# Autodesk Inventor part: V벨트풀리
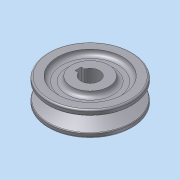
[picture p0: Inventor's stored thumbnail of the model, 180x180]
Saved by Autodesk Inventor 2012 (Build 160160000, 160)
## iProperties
Created: 2015-03
Part Number: V벨트풀리
Material: 강
Document SubType Name: Modeling
Designer: KYOUNG IL JANG
Density: 1 g/cm^3
CustomPartVersion: 1
Author: KYOUNG IL JANG
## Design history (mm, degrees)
sketch "주 스케치"
  geometry: L1 (0, 16)-(27, 16); L2 (27, 16)-(27, 12.861); L3 (27, 12.861)-(16, 9.498); L4 (16, 9.498)-(16, 6.502); L5 (16, 6.502)-(27, 3.139); L6 (27, 3.139)-(27, 0); L7 (27, 0)-(0, 0); L8 (25, 12.25)-(25, 3.75); L9 (16, 8)-(25, 8); L10 (27, 12.861)-(27, 3.139); L11 (0, -3)-(0, 18) reference; L12 (0, 0)-(0, 16)
  constraints: 22 end point, 5 perpendicular, 2 collinear, 2 midpoint, 2 point on line, 1 parallel
  dimensions: "d0" = 8.5 distance of L8.start L8.end (= da_Bw); "d1" = 34 deg angle of L3 L5 (= da_Alfa); "d2" = 2 distance between parallel lines of L2 L8 (= da_c); "d6" = 16 distance between parallel lines of L7 L1 (computed from d5, da_ng, da_Sg); "d21" = 50 diameter of L8 L11 (= da_Dw); "d25" = 11 distance between parallel lines of L4 L10 (= da_Hd); "d27" = 8 distance between parallel lines of L7 L9 (= da_Se)
node "벨트 평면"
revolve "본체" stored, may be unused: angle "d7" = 90 deg
revolve "그루브" stored, may be unused: angle "d15" = 90 deg
feature "허브 키홈"
fillet "모깎기3" dims "d28" = 0.5, "d29" = 1, "d30" = 1
sketch "스케치2"
  geometry: C1 r 12 at (0, 0); C2 r 21 at (0, 0); 1 further point
  constraints: 2 centre point, 2 coincident
  dimensions: "d31" = 24 diameter of C1; "d32" = 42 diameter of C2
extrude "돌출1" cut sketch "스케치2" distance "d33" = 3; taper "d34" = 0 deg
fillet "모깎기4" dims "d35" = 3
node "작업 평면2"
body "Solid1"
pattern_linear "그루브 패턴" dims "d18" = 12 (= da_Sg)
mirror "대칭1"
other parameters: "d5" = 8 (= da_Se), "da_Bw" = 8.5 [user parameter; used in 1 equation term], "da_Alfa" = 34 deg [user parameter; used in 1 equation term], "da_c" = 2 [user parameter; used in 1 equation term], "da_Dw" = 50 [user parameter; used in 1 equation term], "da_Hd" = 11 [user parameter; used in 1 equation term], "da_Se" = 8 [user parameter; used in 2 equation terms], "da_Sg" = 12 [user parameter; used in 2 equation terms], "da_r1" = 0 [user parameter], "da_r2" = 0 [user parameter], "d24" = 0, "d26" = 0
